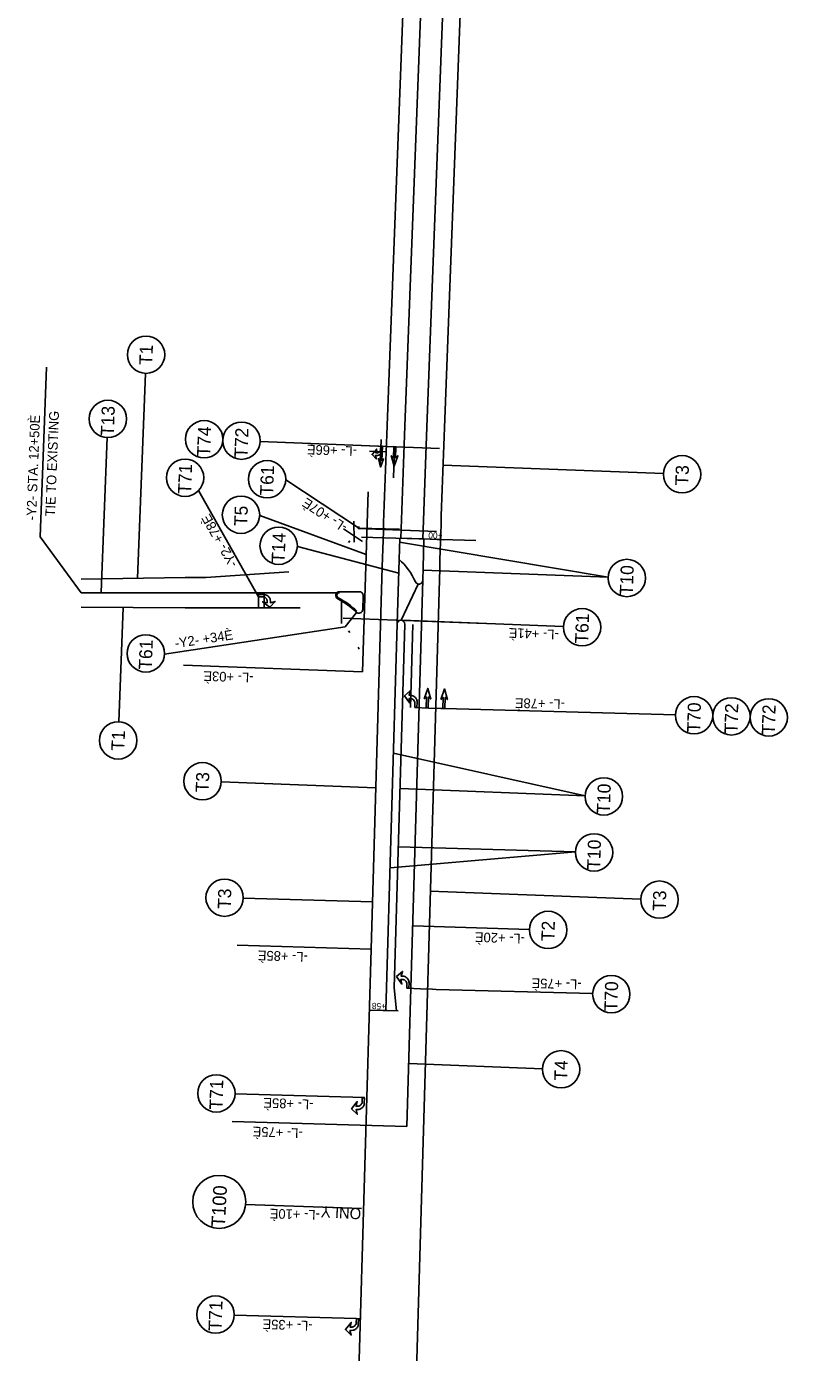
# Model space of a CAD drawing. Extents: x 1657109 to 2100937, y 684916 to 883211.
# Drawn here: x 2097445 to 2097995, y 686330 to 687289 of the extents above; entities that cross this region are included whole.
import ezdxf

# ---------------------------------------------------------------- set-up
doc = ezdxf.new("R2010")
doc.units = 0
for name, color, linetype in [('Old_Level_63', 7, 'Continuous'), ('Prop CMT Pvmt Gravel', 7, 'Continuous'), ('Prop Conc 1ft 6in Curb and Gutter', 7, 'Continuous'), ('Prop Conc 2ft 6in Curb and Gutter', 7, 'Continuous'), ('Prop Conc Curb 8in x 18in', 7, 'Continuous'), ('Prop Conc Curb and Gutter', 7, 'Continuous'), ('Prop Dimension', 7, 'Continuous'), ('Prop DSN Text', 7, 'Continuous'), ('Prop EOT', 7, 'Continuous'), ('Prop Guardrail Anchor Unit CELL', 7, 'Continuous'), ('Prop Lane Arrow CELL', 7, 'Continuous'), ('Prop Lane Lines', 7, 'Continuous'), ('Prop Paved Shoulder', 7, 'Continuous'), ('Prop Rem of Exist Asph Pvmt', 7, 'Continuous'), ('Prop Sign E', 7, 'Continuous'), ('Prop Sign F 2 Digit US Shield in Box CELL', 7, 'Continuous'), ('Prop VPT Ditch Grade Right Label', 7, 'Continuous'), ('Scratch_Level_1', 7, 'Continuous'), ('Scratch_Level_3', 7, 'Continuous'), ('Scratch_Level_5', 7, 'Continuous'), ('Scratch_Level_7', 7, 'Continuous')]:
    doc.layers.add(name, color=color, linetype=linetype)

msp = doc.modelspace()

# ---------------------------------------------------------------- linework, layer by layer
at = {"layer": 'Old_Level_63'}
msp.add_lwpolyline([(2097702.55, 686985.57), (2097702.06, 686975.31), (2097703.4, 686976.43), (2097701.24, 686970.5), (2097699.65, 686976.61), (2097700.88, 686975.37), (2097701.09, 686979.83), (2097700.53, 686979.43), (2097700.1, 686979.2), (2097699.56, 686979.04), (2097699.12, 686978.96), (2097698.57, 686978.91), (2097697.59, 686978.98), (2097698.25, 686976.28), (2097695.04, 686979.5), (2097698.4, 686983.5), (2097697.68, 686980.86), (2097698.45, 686980.84), (2097698.91, 686980.84), (2097699.37, 686980.93), (2097699.77, 686981.12), (2097700.18, 686981.33), (2097700.6, 686981.72), (2097700.93, 686982.22), (2097701.15, 686982.76), (2097701.27, 686983.38), (2097701.37, 686985.63)], close=True, dxfattribs=at)
msp.add_lwpolyline([(2097702.55, 686985.57), (2097702.06, 686975.31), (2097703.4, 686976.43), (2097701.24, 686970.5), (2097699.65, 686976.61), (2097700.88, 686975.37), (2097701.09, 686979.83), (2097700.53, 686979.43), (2097700.1, 686979.2), (2097699.56, 686979.04), (2097699.12, 686978.96), (2097698.57, 686978.91), (2097697.59, 686978.98), (2097698.25, 686976.28), (2097695.04, 686979.5), (2097698.4, 686983.5), (2097697.68, 686980.86), (2097698.45, 686980.84), (2097698.91, 686980.84), (2097699.37, 686980.93), (2097699.77, 686981.12), (2097700.18, 686981.33), (2097700.6, 686981.72), (2097700.93, 686982.22), (2097701.15, 686982.76), (2097701.27, 686983.38), (2097701.37, 686985.63)], close=True, dxfattribs=at)
at = {"layer": 'Prop CMT Pvmt Gravel'}
for p, q in [((2097455.19, 686919.95), (2097459.9, 687042.76)), ((2097531.29, 687038.26), (2097525.6, 686890.13)), ((2097503.67, 686991.81), (2097499.39, 686880.1)), ((2097711.82, 686985.21), (2097614.23, 686989.05)), ((2097746.35, 686971.9), (2097905.55, 686965.8)), ((2097632.74, 686961.18), (2097685.15, 686926.46)), ((2097613.89, 686935.48), (2097690.72, 686907.35)), ((2097484.96, 686879.59), (2097455.19, 686919.95)), ((2097732.56, 686918.49), (2097746.82, 686917.94)), ((2097641.1, 686913.1), (2097714.32, 686893.79)), ((2097865.62, 686890.81), (2097714.98, 686916.12)), ((2097865.62, 686890.81), (2097731.89, 686895.94)), ((2097515.34, 686869.01), (2097512.17, 686786.35)), ((2097716.52, 686859.69), (2097833.31, 686855.21)), ((2097545.11, 686835.23), (2097675.53, 686854.99)), ((2097688.23, 686822.33), (2097558.76, 686827.28)), ((2097849.02, 686732.88), (2097710.53, 686763.58)), ((2097697.8, 686738.56), (2097586.08, 686742.85)), ((2097849.02, 686732.88), (2097715.29, 686738.01)), ((2097841.95, 686692.29), (2097708.13, 686680.84)), ((2097714.07, 686696), (2097841.95, 686692.29)), ((2097602, 686658.76), (2097695.4, 686656.04)), ((2097889.24, 686658.14), (2097737.15, 686663.97)), ((2097724.41, 686638.7), (2097808.78, 686636.25)), ((2097597.6, 686624.75), (2097694.41, 686621.93)), ((2097705.12, 686577.49), (2097693.21, 686577.84)), ((2097721.51, 686539.17), (2097818.12, 686535.47)), ((2097596.09, 686517.25), (2097689.49, 686514.75)), ((2097593.89, 686497.36), (2097720.19, 686493.68)), ((2097603.74, 686437.23), (2097687.44, 686434.52))]:
    msp.add_line(p, q, dxfattribs=at)
for points in [[(2097613.05, 686876.78), (2097613.05, 686876.71), (2097569.79, 686953.52)], [(2097725.94, 686796.77), (2097735.89, 686796.27), (2097744.65, 686796.02), (2097747.29, 686795.96), (2097914.18, 686791.43)], [(2097720.12, 686593.66), (2097730.07, 686593.16), (2097738.83, 686592.91), (2097741.47, 686592.85), (2097854.4, 686589.79)], [(2097686.64, 686354.72), (2097685.21, 686354.76), (2097683.71, 686354.8), (2097595.49, 686357.23)]]:
    msp.add_lwpolyline(points, dxfattribs=at)
for centre, radius in [((2097531.8, 687051.75), 13.5), ((2097504.19, 687005.3), 13.5), ((2097573.76, 686990.6), 13.5), ((2097600.74, 686989.57), 13.5), ((2097559.99, 686962.79), 13.5), ((2097619.25, 686961.7), 13.5), ((2097919.04, 686965.28), 13.5), ((2097600.4, 686935.99), 13.5), ((2097627.61, 686913.62), 13.5), ((2097879.11, 686890.29), 13.5), ((2097846.8, 686854.69), 13.5), ((2097531.62, 686835.75), 13.5), ((2097927.67, 686791.04), 13.5), ((2097954.66, 686790.26), 13.5), ((2097981.65, 686789.47), 13.5), ((2097511.65, 686772.86), 13.5), ((2097572.59, 686743.36), 13.5), ((2097862.51, 686732.37), 13.5), ((2097855.45, 686691.89), 13.5), ((2097588.51, 686659.15), 13.5), ((2097902.73, 686657.75), 13.5), ((2097822.27, 686635.86), 13.5), ((2097867.9, 686589.39), 13.5), ((2097831.62, 686535.07), 13.5), ((2097582.6, 686517.64), 13.5), ((2097584.7, 686439.18), 19.14), ((2097582, 686357.72), 13.5)]:
    msp.add_circle(centre, radius, dxfattribs=at)
at = {"layer": 'Prop Conc 1ft 6in Curb and Gutter'}
msp.add_line((2097723.1, 686593.64), (2097731.68, 686888.92), dxfattribs=at)
at = {"layer": 'Prop Conc 2ft 6in Curb and Gutter'}
msp.add_line((2097720.19, 686493.68), (2097723.1, 686593.64), dxfattribs=at)
at = {"layer": 'Prop Conc Curb 8in x 18in'}
msp.add_line((2097770.13, 686917.32), (2097687.33, 686919.89), dxfattribs=at)
for points in [[(2097776.98, 686857.37), (2097712.4, 686859.85), (2097674.11, 686861.32)], [(2097713.96, 686577.23), (2097705.87, 686577.47), (2097702.92, 686577.56)]]:
    msp.add_lwpolyline(points, dxfattribs=at)
at = {"layer": 'Prop Conc Curb and Gutter'}
for p, q in [((2097715.07, 686919.03), (2097714.61, 686903.76)), ((2097671.6, 686880.39), (2097685.83, 686880.4)), ((2097688.29, 686867.51), (2097688.58, 686877.57)), ((2097705.12, 686577.49), (2097713.25, 686857.04)), ((2097711.1, 686593.99), (2097718.75, 686856.88)), ((2097712.62, 686577.27), (2097711.1, 686593.99))]:
    msp.add_line(p, q, dxfattribs=at)
msp.add_lwpolyline([(2097732.56, 686918.49), (2097731.93, 686897.53), (2097731.68, 686888.92), (2097731.63, 686888.56)], dxfattribs=at)
for centre, radius, start, end in [((2097681.44, 686867.35), 49.25, 24.18273, 47.67479), ((2097728.88, 686888.65), 2.75, 204.18273, 358.08201), ((2097671.6, 686877.64), 2.75, 90.01603, 242.29783), ((2097685.83, 686877.65), 2.75, 358.33483, 90.01603), ((2097643.25, 686823.64), 58.25, 46.10307, 62.29783), ((2097685.54, 686867.59), 2.75, 226.10307, 358.33483), ((2097716, 686856.96), 2.75, 358.33483, 178.33483)]:
    msp.add_arc(centre, radius, start, end, dxfattribs=at)
at = {"layer": 'Prop Dimension'}
for p, q in [((2097687.31, 686986.15), (2097743.84, 686983.98)), ((2097693.33, 686985.92), (2097705.32, 686985.46)), ((2097701.02, 686971.35), (2097701.75, 686990.32)), ((2097705.32, 686985.46), (2097717.31, 686985)), ((2097711.32, 686985.23), (2097710.45, 686962.63)), ((2097693.18, 686981.92), (2097705.17, 686981.46)), ((2097685.01, 686926.19), (2097685.74, 686927.59)), ((2097685.01, 686926.19), (2097741.54, 686924.03)), ((2097679.02, 686917.13), (2097678.02, 686915.92)), ((2097613.05, 686868.63), (2097613.05, 686879.63)), ((2097617.05, 686868.63), (2097617.05, 686879.63)), ((2097613.05, 686870.75), (2097613.05, 686874.13)), ((2097673.06, 686857.34), (2097673.05, 686873.69)), ((2097679.07, 686850.88), (2097678.09, 686852.11)), ((2097685.07, 686840.23), (2097685.63, 686838.77))]:
    msp.add_line(p, q, dxfattribs=at)
at = {"layer": 'Prop DSN Text'}
for p, q in [((2097674.47, 686925.76), (2097679.48, 686922.45)), ((2097679.48, 686922.45), (2097688.2, 686916.69))]:
    msp.add_line(p, q, dxfattribs=at)
msp.add_lwpolyline([(2097682.02, 686916.22), (2097682.02, 686917.44), (2097682.01, 686931.3)], dxfattribs=at)
at = {"layer": 'Prop EOT'}
for p, q in [((2097705.89, 687000.49), (2097764.51, 688529.18)), ((2097747.36, 686998.9), (2097805.98, 688527.59)), ((2097694.41, 686621.93), (2097702.44, 686898.39)), ((2097721.15, 686113.61), (2097743.93, 686897.18))]:
    msp.add_line(p, q, dxfattribs=at)
for radius in [11020.75, 10979.25]:
    msp.add_arc((2108718.54, 686578.14), radius, 177.803699, 178.33483, dxfattribs=at)
at = {"layer": 'Prop Guardrail Anchor Unit CELL'}
for p, q in [((2097559.96, 686890.61), (2097484.96, 686889.56)), ((2097559.96, 686890.61), (2097574.93, 686890.62)), ((2097634.95, 686894.7), (2097574.93, 686890.62)), ((2097484.96, 686869.28), (2097559.96, 686868.61)), ((2097559.96, 686868.61), (2097643.23, 686868.64))]:
    msp.add_line(p, q, dxfattribs=at)
at = {"layer": 'Prop Lane Arrow CELL'}
for p, q in [((2097690.45, 686898.74), (2097692.15, 686952.6)), ((2097688.23, 686822.33), (2097690.45, 686898.74))]:
    msp.add_line(p, q, dxfattribs=at)
at = {"layer": 'Prop Lane Lines'}
for p, q in [((2097714.98, 686925.56), (2097684.9, 686926.43)), ((2097715.99, 686859.71), (2097728.37, 686885.95)), ((2097683.91, 686865.38), (2097675.53, 686854.99))]:
    msp.add_line(p, q, dxfattribs=at)
at = {"layer": 'Prop Paved Shoulder'}
for points in [[(2097725.95, 686796.78), (2097727.44, 686796.73), (2097727.56, 686800.6), (2097727.54, 686801.32), (2097727.46, 686801.87), (2097727.29, 686802.46), (2097727.04, 686802.97), (2097726.8, 686803.35), (2097726.38, 686803.86), (2097726.02, 686804.2), (2097725.58, 686804.57), (2097725, 686804.94), (2097724.53, 686805.14), (2097723.9, 686805.35), (2097723.03, 686805.49), (2097721.82, 686805.53), (2097722.92, 686808.87), (2097718.56, 686805.12), (2097722.4, 686799.75), (2097721.75, 686803.15), (2097722.75, 686803.12), (2097723.31, 686803.07), (2097723.83, 686802.92), (2097724.22, 686802.72), (2097724.73, 686802.4), (2097725.08, 686802.1), (2097725.47, 686801.59), (2097725.73, 686801.02), (2097725.93, 686800.45), (2097726.03, 686799.65)], [(2097725.94, 686796.77), (2097727.44, 686796.73), (2097727.56, 686800.6), (2097727.54, 686801.32), (2097727.46, 686801.87), (2097727.29, 686802.46), (2097727.04, 686802.97), (2097726.79, 686803.35), (2097726.38, 686803.86), (2097726.01, 686804.2), (2097725.58, 686804.57), (2097725, 686804.94), (2097724.53, 686805.14), (2097723.9, 686805.35), (2097723.03, 686805.49), (2097721.82, 686805.53), (2097722.92, 686808.87), (2097718.56, 686805.12), (2097722.4, 686799.75), (2097721.75, 686803.15), (2097722.75, 686803.12), (2097723.31, 686803.07), (2097723.83, 686802.92), (2097724.22, 686802.72), (2097724.73, 686802.39), (2097725.08, 686802.1), (2097725.47, 686801.59), (2097725.73, 686801.02), (2097725.93, 686800.45), (2097726.03, 686799.65)], [(2097720.15, 686593.73), (2097721.65, 686593.69), (2097721.76, 686597.56), (2097721.75, 686598.27), (2097721.67, 686598.82), (2097721.5, 686599.42), (2097721.25, 686599.92), (2097721, 686600.31), (2097720.59, 686600.81), (2097720.22, 686601.15), (2097719.78, 686601.52), (2097719.2, 686601.89), (2097718.74, 686602.1), (2097718.11, 686602.3), (2097717.24, 686602.45), (2097716.03, 686602.48), (2097717.13, 686605.82), (2097712.77, 686602.07), (2097716.61, 686596.71), (2097715.96, 686600.1), (2097716.96, 686600.07), (2097717.52, 686600.03), (2097718.03, 686599.87), (2097718.43, 686599.67), (2097718.94, 686599.35), (2097719.29, 686599.06), (2097719.67, 686598.55), (2097719.94, 686597.97), (2097720.14, 686597.4), (2097720.24, 686596.6)], [(2097720.15, 686593.73), (2097721.65, 686593.68), (2097721.76, 686597.56), (2097721.74, 686598.27), (2097721.67, 686598.82), (2097721.49, 686599.42), (2097721.25, 686599.92), (2097721, 686600.3), (2097720.59, 686600.81), (2097720.22, 686601.15), (2097719.78, 686601.52), (2097719.2, 686601.89), (2097718.74, 686602.09), (2097718.1, 686602.3), (2097717.23, 686602.45), (2097716.03, 686602.48), (2097717.13, 686605.82), (2097712.77, 686602.07), (2097716.61, 686596.71), (2097715.96, 686600.1), (2097716.96, 686600.07), (2097717.52, 686600.03), (2097718.03, 686599.87), (2097718.43, 686599.67), (2097718.94, 686599.35), (2097719.29, 686599.05), (2097719.67, 686598.55), (2097719.94, 686597.97), (2097720.14, 686597.4), (2097720.23, 686596.6)]]:
    msp.add_lwpolyline(points, close=True, dxfattribs=at)
at = {"layer": 'Prop Rem of Exist Asph Pvmt'}
msp.add_line((2097681.55, 686179.67), (2097694.41, 686621.93), dxfattribs=at)
at = {"layer": 'Prop Sign E'}
msp.add_line((2097724.53, 686856.73), (2097722.79, 686796.76), dxfattribs=at)
at = {"layer": 'Prop Sign F 2 Digit US Shield in Box CELL'}
for centre, radius, start, end in [((2097671.56, 686877.66), 2, 90.20192, 242.48372), ((2097643.44, 686823.68), 58.87, 46.28895, 62.48372)]:
    msp.add_arc(centre, radius, start, end, dxfattribs=at)
at = {"layer": 'Prop VPT Ditch Grade Right Label'}
msp.add_line((2097713.25, 686857.04), (2097714.61, 686903.76), dxfattribs=at)
at = {"layer": 'Scratch_Level_1'}
msp.add_line((2097484.96, 686879.59), (2097669.72, 686879.64), dxfattribs=at)
at = {"layer": 'Scratch_Level_3'}
for points in [[(2097613.05, 686876.78), (2097613.05, 686878.28), (2097616.92, 686878.28), (2097617.64, 686878.24), (2097618.18, 686878.15), (2097618.77, 686877.96), (2097619.27, 686877.7), (2097619.65, 686877.44), (2097620.14, 686877.02), (2097620.47, 686876.64), (2097620.83, 686876.19), (2097621.18, 686875.6), (2097621.37, 686875.13), (2097621.56, 686874.49), (2097621.68, 686873.62), (2097621.68, 686872.41), (2097625.05, 686873.41), (2097621.18, 686869.16), (2097615.93, 686873.16), (2097619.3, 686872.41), (2097619.3, 686873.41), (2097619.27, 686873.97), (2097619.13, 686874.49), (2097618.94, 686874.89), (2097618.63, 686875.41), (2097618.35, 686875.76), (2097617.85, 686876.16), (2097617.28, 686876.45), (2097616.72, 686876.66), (2097615.92, 686876.78)], [(2097613.05, 686876.78), (2097613.05, 686878.28), (2097616.92, 686878.28), (2097617.64, 686878.24), (2097618.18, 686878.15), (2097618.77, 686877.96), (2097619.27, 686877.7), (2097619.65, 686877.44), (2097620.14, 686877.02), (2097620.47, 686876.64), (2097620.83, 686876.19), (2097621.18, 686875.6), (2097621.37, 686875.13), (2097621.56, 686874.49), (2097621.68, 686873.62), (2097621.68, 686872.41), (2097625.05, 686873.41), (2097621.18, 686869.16), (2097615.93, 686873.16), (2097619.3, 686872.41), (2097619.3, 686873.41), (2097619.27, 686873.97), (2097619.13, 686874.49), (2097618.94, 686874.89), (2097618.63, 686875.41), (2097618.35, 686875.76), (2097617.85, 686876.16), (2097617.28, 686876.45), (2097616.72, 686876.66), (2097615.92, 686876.78)], [(2097687.99, 686514.56), (2097689.49, 686514.53), (2097689.43, 686510.66), (2097689.38, 686509.94), (2097689.27, 686509.4), (2097689.07, 686508.81), (2097688.81, 686508.32), (2097688.54, 686507.95), (2097688.11, 686507.46), (2097687.72, 686507.14), (2097687.27, 686506.79), (2097686.67, 686506.44), (2097686.2, 686506.26), (2097685.56, 686506.08), (2097684.68, 686505.98), (2097683.47, 686506), (2097684.42, 686502.61), (2097680.23, 686506.56), (2097684.32, 686511.74), (2097683.51, 686508.38), (2097684.51, 686508.36), (2097685.07, 686508.38), (2097685.6, 686508.52), (2097686, 686508.7), (2097686.52, 686509), (2097686.88, 686509.28), (2097687.29, 686509.76), (2097687.59, 686510.33), (2097687.81, 686510.89), (2097687.94, 686511.68)], [(2097687.99, 686514.56), (2097689.49, 686514.53), (2097689.43, 686510.66), (2097689.38, 686509.94), (2097689.27, 686509.4), (2097689.07, 686508.81), (2097688.81, 686508.32), (2097688.54, 686507.95), (2097688.11, 686507.46), (2097687.72, 686507.14), (2097687.27, 686506.79), (2097686.67, 686506.44), (2097686.2, 686506.26), (2097685.56, 686506.08), (2097684.68, 686505.98), (2097683.47, 686506), (2097684.42, 686502.61), (2097680.23, 686506.56), (2097684.32, 686511.74), (2097683.51, 686508.38), (2097684.51, 686508.36), (2097685.07, 686508.38), (2097685.6, 686508.52), (2097686, 686508.7), (2097686.52, 686509), (2097686.88, 686509.28), (2097687.29, 686509.76), (2097687.59, 686510.33), (2097687.81, 686510.89), (2097687.94, 686511.68)], [(2097683.71, 686354.8), (2097685.21, 686354.76), (2097685.1, 686350.89), (2097685.04, 686350.17), (2097684.93, 686349.63), (2097684.72, 686349.05), (2097684.45, 686348.56), (2097684.18, 686348.19), (2097683.74, 686347.71), (2097683.35, 686347.39), (2097682.89, 686347.04), (2097682.29, 686346.71), (2097681.81, 686346.53), (2097681.17, 686346.36), (2097680.29, 686346.27), (2097679.09, 686346.3), (2097679.99, 686342.91), (2097675.85, 686346.9), (2097680, 686352.03), (2097679.16, 686348.68), (2097680.16, 686348.65), (2097680.72, 686348.67), (2097681.24, 686348.79), (2097681.65, 686348.97), (2097682.18, 686349.26), (2097682.54, 686349.54), (2097682.95, 686350.02), (2097683.25, 686350.58), (2097683.48, 686351.14), (2097683.63, 686351.93)], [(2097683.71, 686354.8), (2097685.21, 686354.76), (2097685.1, 686350.89), (2097685.04, 686350.17), (2097684.93, 686349.63), (2097684.72, 686349.05), (2097684.45, 686348.56), (2097684.18, 686348.19), (2097683.74, 686347.71), (2097683.35, 686347.39), (2097682.89, 686347.04), (2097682.29, 686346.71), (2097681.81, 686346.53), (2097681.17, 686346.36), (2097680.29, 686346.27), (2097679.09, 686346.3), (2097679.99, 686342.91), (2097675.85, 686346.9), (2097680, 686352.03), (2097679.16, 686348.68), (2097680.16, 686348.65), (2097680.72, 686348.67), (2097681.24, 686348.79), (2097681.65, 686348.97), (2097682.18, 686349.26), (2097682.54, 686349.54), (2097682.95, 686350.02), (2097683.25, 686350.58), (2097683.48, 686351.14), (2097683.63, 686351.93)]]:
    msp.add_lwpolyline(points, close=True, dxfattribs=at)
at = {"layer": 'Scratch_Level_5'}
for points in [[(2097708.98, 686978.8), (2097710.56, 686977.25), (2097710.79, 686985.25), (2097712.29, 686985.21), (2097712.06, 686977.21), (2097713.72, 686978.66), (2097711.13, 686971.11)], [(2097708.98, 686978.8), (2097710.56, 686977.25), (2097710.79, 686985.25), (2097712.29, 686985.21), (2097712.06, 686977.21), (2097713.72, 686978.66), (2097711.13, 686971.11)], [(2097732.7, 686802.89), (2097734.37, 686804.35), (2097734.14, 686796.35), (2097735.64, 686796.31), (2097735.87, 686804.3), (2097737.45, 686802.76), (2097735.3, 686810.45)], [(2097732.7, 686802.89), (2097734.37, 686804.35), (2097734.14, 686796.35), (2097735.64, 686796.31), (2097735.87, 686804.3), (2097737.45, 686802.76), (2097735.3, 686810.45)], [(2097744.71, 686802.54), (2097746.38, 686803.99), (2097746.15, 686795.99), (2097747.64, 686795.95), (2097747.88, 686803.95), (2097749.46, 686802.4), (2097747.31, 686810.09)], [(2097744.71, 686802.54), (2097746.38, 686803.99), (2097746.15, 686795.99), (2097747.64, 686795.95), (2097747.88, 686803.95), (2097749.46, 686802.4), (2097747.31, 686810.09)]]:
    msp.add_lwpolyline(points, close=True, dxfattribs=at)
at = {"layer": 'Scratch_Level_7'}
msp.add_lwpolyline([(2097715.82, 686919.01), (2097718.63, 687000), (2097757.3, 688008.28), (2097773.28, 688007.66), (2097734.62, 686999.39), (2097731.81, 686918.51)], close=True, dxfattribs=at)

# ---------------------------------------------------------------- texts
at = {"layer": 'Prop CMT Pvmt Gravel'}
for s, height, rotation, p in [('T1', 9.45, 87.8037, (2097536.24, 687044.08)), ('T13', 9.45, 87.8037, (2097508.44, 686992.76)), ('-Y2- STA. 12+50È', 7, 87.8037, (2097452.33, 686931.95)), ('TIE TO EXISTING', 7, 87.8037, (2097466, 686934.65)), ('T74', 9.45, 87.8037, (2097578, 686977.97)), ('T72', 9.45, 87.8037, (2097604.99, 686976.97)), ('-L- +66È', 7, 177.8037, (2097684.3, 686985.34)), ('T71', 9.45, 87.8037, (2097564.26, 686950.87)), ('T61', 9.45, 87.8037, (2097623.52, 686949.78)), ('T3', 9.45, 87.8037, (2097923.45, 686956.99)), ('-L- +07È', 7, 146.75961, (2097677.97, 686928.83)), ('-Y2- +78È', 7, 119.51449, (2097598.43, 686900.42)), ('T5', 9.45, 87.8037, (2097604.81, 686927.66)), ('T14', 9.45, 87.8037, (2097631.86, 686900.99)), ('+00', 4.5, 177.8037, (2097746, 686923.08)), ('T10', 9.45, 87.8037, (2097883.35, 686877.62)), ('T61', 9.45, 87.8037, (2097851.07, 686842.77)), ('-Y2- +34È', 7, 8.61411, (2097553.1, 686839.59)), ('-L- +41È', 7, 177.8037, (2097830.06, 686852.74)), ('T61', 9.45, 87.8037, (2097535.9, 686823.83)), ('-L- +03È', 7, 177.8037, (2097609.53, 686821.59)), ('-L- +78È', 7, 178.42513, (2097834.46, 686802.41)), ('T70', 9.45, 88.33483, (2097932.03, 686778.41)), ('T72', 9.45, 88.33483, (2097959.02, 686777.7)), ('T72', 9.45, 88.33483, (2097986.01, 686776.92)), ('T1', 9.45, 87.8037, (2097516.08, 686765.19)), ('T3', 9.45, 87.8037, (2097577, 686735.07)), ('T10', 9.45, 87.8037, (2097866.76, 686719.69)), ('T10', 9.45, 88.33483, (2097859.81, 686679.26)), ('T3', 9.45, 88.33483, (2097592.99, 686650.9)), ('T3', 9.45, 88.33483, (2097907.22, 686649.5)), ('T2', 9.45, 88.33483, (2097826.75, 686627.55)), ('-L- +20È', 7, 177.8037, (2097805.63, 686632.86)), ('-L- +85È', 7, 177.8037, (2097648.82, 686619.63)), ('-L- +75È', 7, 178.42513, (2097846.52, 686599.89)), ('T70', 9.45, 88.33483, (2097872.26, 686576.76)), ('+58', 4.5, 178.33954, (2097705.21, 686582.85)), ('T4', 9.45, 88.33483, (2097836.1, 686526.73)), ('T71', 9.45, 88.33483, (2097586.98, 686505.76)), ('-L- +85È', 7, 177.8037, (2097652.85, 686513.05)), ('-L- +75È', 7, 177.8037, (2097645.12, 686492.24)), ('T100', 9.875, 86.9833, (2097588.73, 686420.8)), ('-L- +10È', 7, 178.14565, (2097657.44, 686433.12)), ('ONLY', 8, 176.83716, (2097687.44, 686434.52)), ('T71', 9.45, 87.89056, (2097586.29, 686345.81)), ('-L- +35È', 7, 177.8037, (2097652.24, 686353.03))]:
    msp.add_text(s, height=height, rotation=rotation, dxfattribs=at).set_placement(p)

doc.saveas('drawing.dxf')
